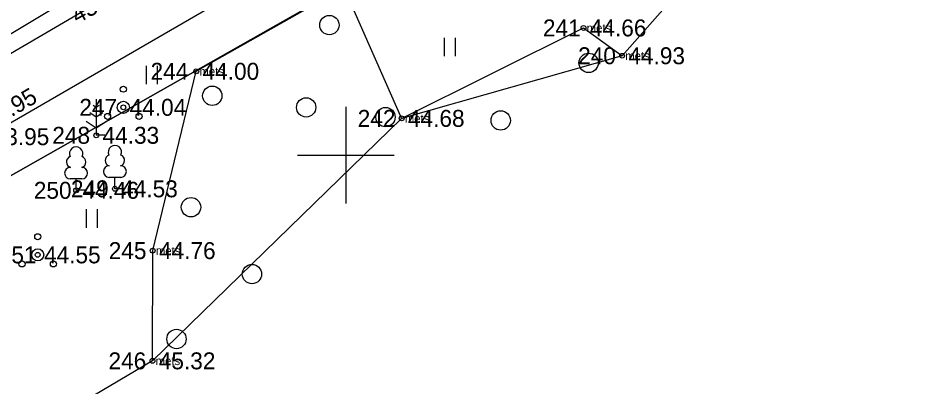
# Model space of a CAD drawing. Extents: x 505800 to 507326, y 6540058 to 6542128.
# Drawn here: x 506386.44 to 506423.99, y 6540340.42 to 6540355.67 of the extents above; entities that cross this region are included whole.
import ezdxf

# ---------------------------------------------------------------- set-up
doc = ezdxf.new("R2010")
doc.units = 0
for name, color, linetype in [('HALJASTUS', 7, 'Continuous'), ('KORGUS-EH2000', 7, 'Continuous'), ('MAAMUDEL', 7, 'Continuous'), ('MOOTKORG-EH2000', 7, 'Continuous'), ('MOOTMPUNKT', 7, 'Continuous'), ('MOOTNR', 7, 'Continuous'), ('MOOTPIIR', 7, 'Continuous'), ('PIIR', 7, 'Continuous'), ('PUU', 7, 'Continuous'), ('TEE', 7, 'Continuous'), ('VORK', 7, 'Continuous')]:
    doc.layers.add(name, color=color, linetype=linetype)

msp = doc.modelspace()

# ---------------------------------------------------------------- linework, layer by layer
at = {"layer": 'HALJASTUS'}
for p, q in [((506404.067, 6540354.855), (506404.067, 6540354.094)), ((506404.522, 6540354.855), (506404.522, 6540354.094)), ((506391.736, 6540353.694), (506391.736, 6540352.933)), ((506392.191, 6540353.694), (506392.191, 6540352.933)), ((506389.254, 6540347.765), (506389.254, 6540347.004)), ((506389.709, 6540347.765), (506389.709, 6540347.004))]:
    msp.add_line(p, q, dxfattribs=at)
for points in [[(506383.074, 6540362.871), (506387.104, 6540358.456), (506388.363, 6540356.347), (506379.473, 6540351.019), (506371.247, 6540346.037), (506370.193, 6540346.236), (506368.863, 6540348.749), (506383.542, 6540357.221), (506381.795, 6540361.969), (506383.074, 6540362.871)], [(506391.999, 6540341.498), (506392.008, 6540346.055), (506393.81, 6540353.469), (506399.916, 6540356.93), (506402.307, 6540351.523), (506409.831, 6540355.263), (506411.426, 6540354.112)]]:
    msp.add_lwpolyline(points, dxfattribs=at)
for centre in [(506399.317, 6540355.381), (506410.041, 6540353.818), (506394.472, 6540352.456), (506398.356, 6540351.976), (506401.639, 6540351.575), (506406.403, 6540351.438), (506393.592, 6540347.849), (506396.114, 6540345.085), (506392.991, 6540342.401)]:
    msp.add_circle(centre, 0.4, dxfattribs=at)
at = {"layer": 'KORGUS-EH2000'}
for centre in [(506409.831, 6540355.263), (506411.426, 6540354.112), (506393.81, 6540353.469), (506390.793, 6540351.979), (506402.307, 6540351.523), (506389.673, 6540350.823), (506388.839, 6540348.548), (506390.444, 6540348.61), (506387.251, 6540345.88), (506392.008, 6540346.055), (506391.999, 6540341.498)]:
    msp.add_circle(centre, 0.1, dxfattribs=at)
at = {"layer": 'MOOTMPUNKT'}
for centre in [(506409.831, 6540355.263), (506411.426, 6540354.112), (506393.81, 6540353.469), (506390.793, 6540351.979), (506402.307, 6540351.523), (506389.673, 6540350.823), (506388.839, 6540348.548), (506390.444, 6540348.61), (506387.251, 6540345.88), (506392.008, 6540346.055), (506391.999, 6540341.498)]:
    msp.add_circle(centre, 0.1, dxfattribs=at)
at = {"layer": 'MOOTPIIR'}
msp.add_lwpolyline([(506495.183, 6540386.603), (506455.807, 6540378.751), (506413.936, 6540356.957), (506411.426, 6540354.112), (506402.307, 6540351.523), (506391.999, 6540341.498), (506380.901, 6540334.942), (506360.247, 6540322.568), (506353.013, 6540324.95), (506332.133, 6540309.036), (506315.598, 6540297.889), (506301.375, 6540281.904), (506292.827, 6540267.673), (506286.653, 6540264.508), (506248.469, 6540250.071)], dxfattribs=at)
at = {"layer": 'PIIR'}
for points in [[(506497.85, 6540391.32), (506462.8, 6540384.69), (506453.27, 6540382.76), (506413.82, 6540364.84), (506374.55, 6540342.6), (506353.59, 6540332.53), (506318.07, 6540309.28), (506308, 6540301.95), (506281.65, 6540275.05), (506272.39, 6540267.75), (506224.13, 6540249.92)], [(506224.13, 6540249.92), (506272.39, 6540267.75), (506281.65, 6540275.05), (506308, 6540301.95), (506318.07, 6540309.28), (506353.59, 6540332.53), (506374.55, 6540342.6), (506413.82, 6540364.84), (506453.27, 6540382.76), (506462.8, 6540384.69), (506495.14, 6540337.45), (506342.85, 6540237.27), (506260.72, 6540195.9), (506215.68, 6540179.69)]]:
    msp.add_lwpolyline(points, dxfattribs=at)
at = {"layer": 'PUU'}
for p, q in [((506389.673, 6540352.323), (506389.673, 6540350.823)), ((506389.673, 6540351.973), (506389.549, 6540352.056)), ((506389.798, 6540352.056), (506389.673, 6540351.973)), ((506389.673, 6540351.573), (506389.407, 6540351.75)), ((506389.94, 6540351.75), (506389.673, 6540351.573)), ((506389.249, 6540351.412), (506389.673, 6540351.129)), ((506389.673, 6540351.129), (506390.098, 6540351.412)), ((506390.033, 6540350.823), (506389.673, 6540350.823)), ((506389.079, 6540349.023), (506388.599, 6540349.023)), ((506388.839, 6540348.548), (506388.839, 6540349.023)), ((506390.684, 6540349.085), (506390.204, 6540349.085)), ((506390.444, 6540348.61), (506390.444, 6540349.085)), ((506389.219, 6540348.548), (506388.839, 6540348.548)), ((506390.824, 6540348.61), (506390.444, 6540348.61))]:
    msp.add_line(p, q, dxfattribs=at)
for centre, radius in [((506390.793, 6540352.729), 0.125), ((506390.793, 6540351.979), 0.25), ((506390.143, 6540351.604), 0.125), ((506391.443, 6540351.604), 0.125), ((506387.251, 6540346.63), 0.125), ((506387.251, 6540345.88), 0.25), ((506386.601, 6540345.505), 0.125), ((506387.901, 6540345.505), 0.125)]:
    msp.add_circle(centre, radius, dxfattribs=at)
for centre, radius, start, end in [((506388.839, 6540350.068), 0.277, 332.5799, 207.4201), ((506390.444, 6540350.13), 0.277, 332.5799, 207.4201), ((506388.669, 6540349.721), 0.233, 109.0217, 253.1415), ((506389.009, 6540349.721), 0.233, 286.8508, 70.9859), ((506390.274, 6540349.783), 0.233, 109.0217, 253.1415), ((506390.614, 6540349.783), 0.233, 286.8508, 70.9859), ((506388.602, 6540349.261), 0.238, 90.0016, 269.3953), ((506389.077, 6540349.261), 0.238, 270.6047, 89.9984), ((506390.207, 6540349.323), 0.238, 90.0016, 269.3953), ((506390.682, 6540349.323), 0.238, 270.6047, 89.9984)]:
    msp.add_arc(centre, radius, start, end, dxfattribs=at)
at = {"layer": 'TEE'}
for points in [[(506478.706, 6540392.058), (506464.091, 6540389.4), (506454.678, 6540387.173), (506446.264, 6540384.451), (506435.18, 6540379.372), (506420.092, 6540372.182), (506407.957, 6540366.228), (506394.897, 6540359.329), (506383.759, 6540352.819), (506372.647, 6540346.37), (506363.224, 6540341.99), (506352.182, 6540336.393), (506347.174, 6540333.201), (506340.898, 6540329.111), (506329.323, 6540321.237)], [(506479.167, 6540389.797), (506464.651, 6540387.028), (506455.166, 6540384.708), (506447.071, 6540382.035), (506436.402, 6540377.232), (506421.232, 6540370.083), (506409.03, 6540364.194), (506396.144, 6540357.137), (506385.127, 6540350.766), (506373.749, 6540344.271), (506364.374, 6540339.718), (506353.506, 6540334.212), (506348.479, 6540331.101), (506342.338, 6540327.065), (506330.786, 6540319.25)]]:
    msp.add_lwpolyline(points, dxfattribs=at)
at = {"layer": 'VORK'}
for p, q in [((506400, 6540352), (506400, 6540348)), ((506398, 6540350), (506402, 6540350))]:
    msp.add_line(p, q, dxfattribs=at)

# ---------------------------------------------------------------- texts
at = {"layer": 'KORGUS-EH2000'}
for s, rotation, p in [(' 43.73', 28.559, (506388.658, 6540355.301)), (' 43.95', 30.0411, (506385.04, 6540350.918))]:
    msp.add_text(s, height=0.7, rotation=rotation, dxfattribs=at).set_placement(p)
for s, p in [(' 44.66', (506409.831, 6540354.913)), (' 44.93', (506411.426, 6540353.762)), (' 44.00', (506393.81, 6540353.119)), (' 44.68', (506402.307, 6540351.173)), (' 44.76', (506392.008, 6540345.705)), (' 44.55', (506387.251, 6540345.53)), (' 45.32', (506391.999, 6540341.148))]:
    msp.add_text(s, height=0.7, dxfattribs=at).set_placement(p)
at = {"layer": 'MAAMUDEL'}
for p in [(506409.831, 6540355.088), (506411.426, 6540353.937), (506393.81, 6540353.294), (506402.307, 6540351.348), (506392.008, 6540345.88), (506391.999, 6540341.323)]:
    msp.add_text(' mets', height=0.35, dxfattribs=at).set_placement(p)
at = {"layer": 'MOOTKORG-EH2000'}
for s, p in [(' 44.66', (506409.831, 6540354.913)), (' 44.93', (506411.426, 6540353.762)), (' 44.00', (506393.81, 6540353.119)), (' 44.04', (506390.793, 6540351.629)), (' 44.68', (506402.307, 6540351.173)), (' 44.33', (506389.673, 6540350.473)), (' 43.95', (506385.127, 6540350.416)), (' 44.53', (506390.444, 6540348.26)), (' 44.46', (506388.839, 6540348.198)), (' 44.76', (506392.008, 6540345.705)), (' 44.55', (506387.251, 6540345.53)), (' 45.32', (506391.999, 6540341.148))]:
    msp.add_text(s, height=0.7, dxfattribs=at).set_placement(p)
at = {"layer": 'MOOTNR'}
for s, p in [('241 ', (506408.151, 6540354.913)), ('240 ', (506409.606, 6540353.762)), ('244 ', (506391.92, 6540353.119)), ('247 ', (506388.973, 6540351.629)), ('242 ', (506400.488, 6540351.173)), ('248 ', (506387.854, 6540350.473)), ('249 ', (506388.625, 6540348.26)), ('250 ', (506387.089, 6540348.198)), ('245 ', (506390.188, 6540345.705)), ('251 ', (506385.641, 6540345.53)), ('246 ', (506390.179, 6540341.148))]:
    msp.add_text(s, height=0.7, dxfattribs=at).set_placement(p)

doc.saveas('drawing.dxf')
